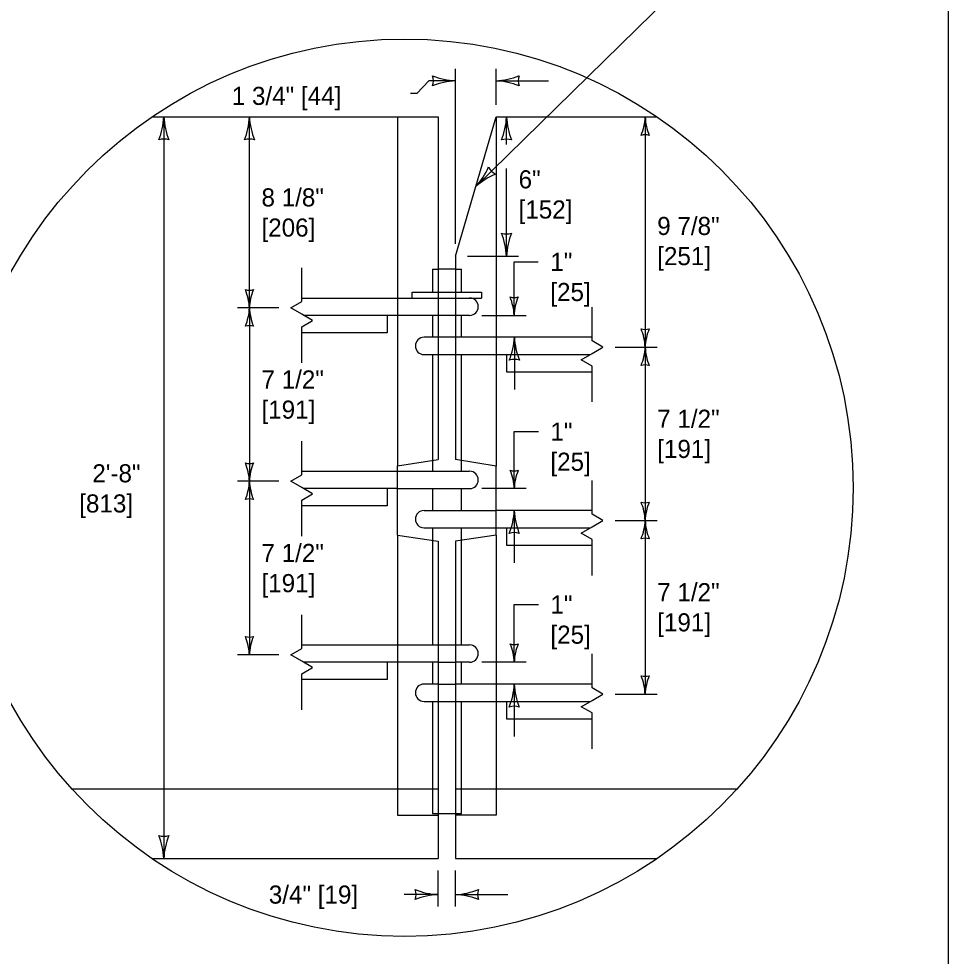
# Model space of a CAD drawing. Extents: x 49991.4 to 50021, y 49987.6 to 50011.4.
# Drawn here: x 50013.668 to 50016.75, y 49992.032 to 49995.141 of the extents above; entities that cross this region are included whole.
import ezdxf

# ---------------------------------------------------------------- set-up
doc = ezdxf.new("R2010")
doc.units = 0
for name, color, linetype in [('Level 1', 7, 'Continuous'), ('Level 2', 7, 'Continuous'), ('Level 3', 7, 'Continuous'), ('Level 4', 7, 'Continuous'), ('Level 6', 7, 'Continuous')]:
    doc.layers.add(name, color=color, linetype=linetype)

msp = doc.modelspace()

# ---------------------------------------------------------------- linework, layer by layer
at = {"layer": 'Level 1'}
for p, q in [((50014.1093, 49994.815), (50015.0589, 49994.815)), ((50015.0589, 49994.815), (50015.0589, 49993.6791)), ((50015.1164, 49994.354), (50015.2508, 49994.815)), ((50015.2508, 49994.815), (50015.7852, 49994.815)), ((50015.1164, 49994.354), (50015.1164, 49993.6791)), ((50015.1164, 49994.3108), (50015.0589, 49994.3108)), ((50015.0589, 49994.234), (50015.1164, 49994.234)), ((50015.0589, 49994.2148), (50015.1164, 49994.2148)), ((50015.1164, 49994.1573), (50015.0589, 49994.1573)), ((50015.1164, 49994.0848), (50015.0589, 49994.0848)), ((50015.0589, 49994.0272), (50015.1164, 49994.0272)), ((50014.9245, 49993.6586), (50015.0589, 49993.6791)), ((50015.0396, 49993.6762), (50015.0396, 49993.6402)), ((50015.2508, 49993.6577), (50015.1164, 49993.6791)), ((50015.1357, 49993.6402), (50015.1357, 49993.676)), ((50014.9245, 49993.4288), (50014.9245, 49993.6586)), ((50014.9245, 49993.6402), (50015.1633, 49993.6402)), ((50015.2508, 49993.4288), (50015.2508, 49993.6577)), ((50014.9245, 49993.5828), (50015.1633, 49993.5828)), ((50015.0396, 49993.5828), (50015.0396, 49993.5102)), ((50015.1357, 49993.5102), (50015.1357, 49993.5828)), ((50015.0121, 49993.5102), (50015.2508, 49993.5102)), ((50015.0121, 49993.4528), (50015.2508, 49993.4528)), ((50015.0396, 49993.4528), (50015.0396, 49993.4113)), ((50015.1357, 49993.4113), (50015.1357, 49993.4528)), ((50014.9245, 49993.4288), (50015.0589, 49993.4084)), ((50015.2508, 49993.4288), (50015.1164, 49993.4084)), ((50015.0589, 49993.4084), (50015.0589, 49992.3567)), ((50015.1164, 49993.4084), (50015.1164, 49992.3567)), ((50015.0589, 49993.0647), (50015.1164, 49993.0647)), ((50015.0589, 49993.0072), (50015.1164, 49993.0072)), ((50015.0589, 49992.9346), (50015.1164, 49992.9346)), ((50015.0589, 49992.8772), (50015.1164, 49992.8772)), ((50015.0589, 49992.5055), (50015.1164, 49992.5055)), ((50014.1091, 49992.3567), (50015.0589, 49992.3567)), ((50015.1164, 49992.3567), (50015.7852, 49992.3567))]:
    msp.add_line(p, q, dxfattribs=at)
msp.add_lwpolyline([(49999.3835, 49998.9992), (50016.7501, 49998.9992), (50016.7501, 49987.7988), (49999.3835, 49987.7988)], close=True, dxfattribs=at)
for centre, start, end in [((50015.1633, 49993.6115), 270, 90), ((50015.0121, 49993.4815), 90, 270)]:
    msp.add_arc(centre, 0.0287, start, end, dxfattribs=at)
at = {"layer": 'Level 3'}
for p, q in [((50016.0589, 49995.4418), (50015.1836, 49994.5845)), ((50015.1164, 49994.394), (50015.1164, 49994.975)), ((50015.2508, 49994.855), (50015.2508, 49994.975)), ((50015.1164, 49994.935), (50015.0279, 49994.935)), ((50015.2508, 49994.935), (50015.4243, 49994.935)), ((50014.1493, 49994.815), (50014.1493, 49992.3567)), ((50014.4331, 49994.1818), (50014.4331, 49994.815)), ((50015.2856, 49994.7243), (50015.2856, 49994.815)), ((50015.7452, 49994.815), (50015.7452, 49994.0518)), ((50015.2856, 49994.354), (50015.2856, 49994.6443)), ((50015.1564, 49994.354), (50015.3256, 49994.354)), ((50015.3107, 49994.1576), (50015.3107, 49994.3347)), ((50015.3107, 49994.3347), (50015.3907, 49994.3347)), ((50014.5301, 49994.1818), (50014.3932, 49994.1818)), ((50014.4331, 49994.1818), (50014.4331, 49993.6072)), ((50015.2033, 49994.1573), (50015.3507, 49994.1573)), ((50015.3116, 49994.0848), (50015.3116, 49993.9113)), ((50015.6453, 49994.0518), (50015.7852, 49994.0518)), ((50015.7452, 49994.0518), (50015.7452, 49993.4771)), ((50015.3111, 49993.7719), (50015.3911, 49993.7719)), ((50015.3111, 49993.5827), (50015.3111, 49993.7719)), ((50014.5301, 49993.6072), (50014.3931, 49993.6072)), ((50014.4331, 49993.6072), (50014.4331, 49993.0317)), ((50015.3511, 49993.5827), (50015.2032, 49993.5827)), ((50015.3111, 49993.5102), (50015.3111, 49993.3368)), ((50015.6453, 49993.4771), (50015.7852, 49993.4771)), ((50015.7452, 49993.4771), (50015.7452, 49992.9016)), ((50015.3111, 49993.0071), (50015.3111, 49993.1985)), ((50015.3111, 49993.1985), (50015.3911, 49993.1985)), ((50014.5301, 49993.0317), (50014.3931, 49993.0317)), ((50015.3511, 49993.0071), (50015.2032, 49993.0071)), ((50015.3111, 49992.9346), (50015.3111, 49992.7611)), ((50015.6453, 49992.9016), (50015.7852, 49992.9016)), ((50015.0589, 49992.1967), (50015.0589, 49992.3167)), ((50015.1164, 49992.1967), (50015.1164, 49992.3167)), ((50015.0589, 49992.2367), (50014.946, 49992.2367)), ((50015.1164, 49992.2367), (50015.2898, 49992.2367))]:
    msp.add_line(p, q, dxfattribs=at)
msp.add_lwpolyline([(50015.0279, 49994.935), (50014.9881, 49994.8926), (50014.9667, 49994.8926)], dxfattribs=at)
msp.add_circle((50014.9472, 49993.5858), 1.4876, dxfattribs=at)
for centre, radius, start, end in [((50015.1256, 49995.1571), 0.2223, 247.456, 267.6395), ((50014.9882, 49994.935), 0.0548, 342.1388, 17.8612), ((50015.1279, 49994.7022), 0.233, 92.8273, 112.0772), ((50015.2393, 49995.1677), 0.233, 272.8273, 292.0772), ((50015.2417, 49994.7128), 0.2223, 67.456, 87.6395), ((50015.3791, 49994.935), 0.0548, 162.1388, 197.8612), ((50013.9271, 49994.8242), 0.2223, 337.456, 357.6395), ((50014.382, 49994.8265), 0.233, 182.8273, 202.0772), ((50014.211, 49994.8242), 0.2223, 337.456, 357.6395), ((50014.6659, 49994.8265), 0.233, 182.8273, 202.0772), ((50015.0634, 49994.8241), 0.2223, 337.456, 357.6395), ((50015.5183, 49994.8264), 0.233, 182.8273, 202.0772), ((50015.5675, 49994.8223), 0.1779, 337.456, 357.6395), ((50015.9314, 49994.8242), 0.1864, 182.8273, 202.0772), ((50015.7452, 49994.7124), 0.0438, 72.1388, 107.8612), ((50014.1493, 49994.6868), 0.0548, 72.1388, 107.8612), ((50014.4331, 49994.6868), 0.0548, 72.1388, 107.8612), ((50015.2856, 49994.6867), 0.0548, 72.1388, 107.8612), ((50015.0126, 49994.7427), 0.233, 317.2321, 336.4819), ((50015.3325, 49994.4194), 0.2223, 111.8608, 132.0443), ((50015.2752, 49994.6742), 0.0548, 206.5436, 242.2659), ((50015.2856, 49994.4822), 0.0548, 252.1388, 287.8612), ((50015.0528, 49994.3425), 0.233, 2.8273, 22.0772), ((50015.5077, 49994.3449), 0.2223, 157.456, 177.6395), ((50014.4331, 49994.2843), 0.0438, 252.1388, 287.8612), ((50014.247, 49994.1726), 0.1864, 2.8273, 22.0772), ((50014.6109, 49994.1744), 0.1779, 157.456, 177.6395), ((50015.3107, 49994.2599), 0.0438, 252.1388, 287.8612), ((50015.1246, 49994.1481), 0.1864, 2.8273, 22.0772), ((50015.4884, 49994.15), 0.1779, 157.456, 177.6395), ((50014.2554, 49994.1891), 0.1779, 337.456, 357.6395), ((50014.6193, 49994.191), 0.1864, 182.8273, 202.0772), ((50014.4331, 49994.0792), 0.0438, 72.1388, 107.8612), ((50015.7452, 49994.1543), 0.0438, 252.1388, 287.8612), ((50015.559, 49994.0426), 0.1864, 2.8273, 22.0772), ((50015.9229, 49994.0444), 0.1779, 157.456, 177.6395), ((50015.0894, 49994.094), 0.2223, 337.456, 357.6395), ((50015.5443, 49994.0963), 0.233, 182.8273, 202.0772), ((50015.5675, 49994.0591), 0.1779, 337.456, 357.6395), ((50015.9314, 49994.0609), 0.1864, 182.8273, 202.0772), ((50015.3116, 49993.9566), 0.0548, 72.1388, 107.8612), ((50015.7452, 49993.9492), 0.0438, 72.1388, 107.8612), ((50014.4331, 49993.7098), 0.0438, 252.1388, 287.8612), ((50014.247, 49993.598), 0.1864, 2.8273, 22.0772), ((50014.6109, 49993.5999), 0.1779, 157.456, 177.6395), ((50015.3111, 49993.6853), 0.0438, 252.1388, 287.8612), ((50015.125, 49993.5735), 0.1864, 2.8273, 22.0772), ((50015.4888, 49993.5754), 0.1779, 157.456, 177.6395), ((50014.2554, 49993.6145), 0.1779, 337.456, 357.6395), ((50014.6193, 49993.6164), 0.1864, 182.8273, 202.0772), ((50014.4331, 49993.5046), 0.0438, 72.1388, 107.8612), ((50015.7452, 49993.5797), 0.0438, 252.1388, 287.8612), ((50015.559, 49993.4679), 0.1864, 2.8273, 22.0772), ((50015.9229, 49993.4698), 0.1779, 157.456, 177.6395), ((50015.089, 49993.5194), 0.2223, 337.456, 357.6395), ((50015.5439, 49993.5217), 0.233, 182.8273, 202.0772), ((50015.5675, 49993.4844), 0.1779, 337.456, 357.6395), ((50015.9314, 49993.4863), 0.1864, 182.8273, 202.0772), ((50015.3111, 49993.382), 0.0548, 72.1388, 107.8612), ((50015.7452, 49993.3745), 0.0438, 72.1388, 107.8612), ((50014.4331, 49993.1342), 0.0438, 252.1388, 287.8612), ((50014.247, 49993.0225), 0.1864, 2.8273, 22.0772), ((50014.6109, 49993.0244), 0.1779, 157.456, 177.6395), ((50015.3111, 49993.1096), 0.0438, 252.1388, 287.8612), ((50015.125, 49992.9979), 0.1864, 2.8273, 22.0772), ((50015.4888, 49992.9997), 0.1779, 157.456, 177.6395), ((50015.7452, 49993.0042), 0.0438, 252.1388, 287.8612), ((50015.559, 49992.8924), 0.1864, 2.8273, 22.0772), ((50015.9229, 49992.8943), 0.1779, 157.456, 177.6395), ((50015.089, 49992.9437), 0.2223, 337.456, 357.6395), ((50015.5438, 49992.946), 0.233, 182.8273, 202.0772), ((50015.3111, 49992.8063), 0.0548, 72.1388, 107.8612), ((50014.1493, 49992.4849), 0.0548, 252.1388, 287.8612), ((50013.9165, 49992.3452), 0.233, 2.8273, 22.0772), ((50014.3714, 49992.3475), 0.2223, 157.456, 177.6395), ((50015.0681, 49992.4588), 0.2223, 247.456, 267.6395), ((50014.9307, 49992.2367), 0.0548, 342.1388, 17.8612), ((50015.0704, 49992.004), 0.233, 92.8273, 112.0772), ((50015.1049, 49992.4694), 0.233, 272.8273, 292.0772), ((50015.1072, 49992.0146), 0.2223, 67.456, 87.6395), ((50015.2446, 49992.2367), 0.0548, 162.1388, 197.8612)]:
    msp.add_arc(centre, radius, start, end, dxfattribs=at)
at = {"layer": 'Level 4'}
for p, q in [((50014.9245, 49994.815), (50014.9245, 49993.6586)), ((50015.2508, 49994.8148), (50015.2508, 49993.6577)), ((50015.0396, 49994.3108), (50015.0589, 49994.3108)), ((50015.0396, 49994.3108), (50015.0396, 49994.234)), ((50015.1164, 49994.3108), (50015.1357, 49994.3108)), ((50015.1357, 49994.234), (50015.1357, 49994.3108)), ((50014.9724, 49994.2148), (50014.9724, 49994.234)), ((50014.9724, 49994.234), (50015.0589, 49994.234)), ((50015.1164, 49994.234), (50015.2028, 49994.234)), ((50015.2028, 49994.234), (50015.2028, 49994.2148)), ((50014.6064, 49994.2148), (50015.0589, 49994.2148)), ((50015.1164, 49994.2148), (50015.2028, 49994.2148)), ((50015.0589, 49994.1573), (50014.6125, 49994.1573)), ((50014.8896, 49994.1573), (50014.8896, 49994.0998)), ((50015.0396, 49994.1573), (50015.0396, 49994.0848)), ((50015.1632, 49994.1573), (50015.1164, 49994.1573)), ((50015.1357, 49994.0848), (50015.1357, 49994.1573)), ((50014.8896, 49994.0998), (50014.6064, 49994.0998)), ((50015.0589, 49994.0848), (50015.0121, 49994.0848)), ((50015.569, 49994.0848), (50015.1164, 49994.0848)), ((50015.0121, 49994.0272), (50015.0589, 49994.0272)), ((50015.0396, 49994.0272), (50015.0396, 49993.6761)), ((50015.1164, 49994.0272), (50015.5626, 49994.0272)), ((50015.1357, 49993.676), (50015.1357, 49994.0272)), ((50015.2857, 49994.0272), (50015.2857, 49993.97)), ((50015.2857, 49993.97), (50015.569, 49993.97)), ((50014.6064, 49993.6402), (50014.9245, 49993.6402)), ((50014.9245, 49993.5828), (50014.6127, 49993.5828)), ((50014.8896, 49993.5828), (50014.8896, 49993.5253)), ((50014.8896, 49993.5253), (50014.6064, 49993.5253)), ((50015.569, 49993.5102), (50015.2508, 49993.5102)), ((50015.2508, 49993.4528), (50015.563, 49993.4528)), ((50015.2857, 49993.4528), (50015.2857, 49993.3952)), ((50014.9245, 49993.4288), (50014.9245, 49992.5004)), ((50015.0396, 49993.4113), (50015.0396, 49993.0647)), ((50015.1357, 49993.0647), (50015.1357, 49993.4113)), ((50015.2508, 49993.4288), (50015.2508, 49992.5004)), ((50015.2857, 49993.3952), (50015.569, 49993.3952)), ((50014.6064, 49993.0647), (50015.0589, 49993.0647)), ((50015.1164, 49993.0647), (50015.1632, 49993.0647)), ((50015.0589, 49993.0072), (50014.6127, 49993.0072)), ((50014.8896, 49993.0072), (50014.8896, 49992.9497)), ((50015.0396, 49993.0072), (50015.0396, 49992.9346)), ((50015.1632, 49993.0072), (50015.1164, 49993.0072)), ((50015.1357, 49992.9346), (50015.1357, 49993.0072)), ((50014.8896, 49992.9497), (50014.6064, 49992.9497)), ((50015.0589, 49992.9346), (50015.0121, 49992.9346)), ((50015.569, 49992.9346), (50015.1164, 49992.9346)), ((50015.0121, 49992.8772), (50015.0589, 49992.8772)), ((50015.0396, 49992.8772), (50015.0396, 49992.5055)), ((50015.1164, 49992.8772), (50015.5629, 49992.8772)), ((50015.1357, 49992.5055), (50015.1357, 49992.8772)), ((50015.2857, 49992.8772), (50015.2857, 49992.8197)), ((50015.2857, 49992.8197), (50015.569, 49992.8197)), ((50015.0589, 49992.5864), (50013.8453, 49992.5864)), ((50016.0491, 49992.5864), (50015.1164, 49992.5864)), ((50014.9245, 49992.5004), (50015.0589, 49992.5004)), ((50015.0396, 49992.5055), (50015.0589, 49992.5055)), ((50015.1164, 49992.5055), (50015.1357, 49992.5055)), ((50015.2508, 49992.5004), (50015.1164, 49992.5004))]:
    msp.add_line(p, q, dxfattribs=at)
for centre, radius, start, end in [((50015.1632, 49994.1861), 0.0288, 270, 90), ((50015.0121, 49994.056), 0.0288, 90, 270), ((50015.1632, 49993.0359), 0.0287, 270, 90), ((50015.0121, 49992.9059), 0.0287, 90, 270)]:
    msp.add_arc(centre, radius, start, end, dxfattribs=at)
at = {"layer": 'Level 6'}
for p, q in [((50014.6064, 49994.2028), (50014.6064, 49994.3148)), ((50014.5701, 49994.1818), (50014.6064, 49994.2028)), ((50014.6064, 49994.1608), (50014.5701, 49994.1818)), ((50014.6427, 49994.14), (50014.6064, 49994.1608)), ((50015.569, 49994.0728), (50015.569, 49994.1848)), ((50014.6064, 49994.119), (50014.6427, 49994.14)), ((50014.6064, 49993.9998), (50014.6064, 49994.119)), ((50015.6053, 49994.0518), (50015.569, 49994.0728)), ((50015.569, 49994.0309), (50015.6053, 49994.0518)), ((50015.5327, 49994.0099), (50015.569, 49994.0309)), ((50015.569, 49993.9889), (50015.5327, 49994.0099)), ((50015.569, 49993.87), (50015.569, 49993.9889)), ((50014.6064, 49993.6283), (50014.6064, 49993.7402)), ((50014.5701, 49993.6072), (50014.6064, 49993.6283)), ((50014.6064, 49993.5864), (50014.5701, 49993.6072)), ((50015.569, 49993.4982), (50015.569, 49993.6102)), ((50014.6427, 49993.5655), (50014.6064, 49993.5864)), ((50014.6064, 49993.5444), (50014.6427, 49993.5655)), ((50014.6064, 49993.4253), (50014.6064, 49993.5444)), ((50015.6053, 49993.4772), (50015.569, 49993.4982)), ((50015.569, 49993.4562), (50015.6053, 49993.4772)), ((50015.5327, 49993.4353), (50015.569, 49993.4562)), ((50015.569, 49993.4144), (50015.5327, 49993.4353)), ((50015.569, 49993.2952), (50015.569, 49993.4144)), ((50014.6064, 49993.0525), (50014.6064, 49993.1647)), ((50014.5701, 49993.0317), (50014.6064, 49993.0525)), ((50014.6064, 49993.0108), (50014.5701, 49993.0317)), ((50014.6427, 49992.9898), (50014.6064, 49993.0108)), ((50015.569, 49992.9227), (50015.569, 49993.0346)), ((50014.6064, 49992.9688), (50014.6427, 49992.9898)), ((50014.6064, 49992.8497), (50014.6064, 49992.9688)), ((50015.6053, 49992.9016), (50015.569, 49992.9227)), ((50015.569, 49992.8807), (50015.6053, 49992.9016)), ((50015.5327, 49992.8597), (50015.569, 49992.8807)), ((50015.569, 49992.8388), (50015.5327, 49992.8597)), ((50015.569, 49992.7197), (50015.569, 49992.8388))]:
    msp.add_line(p, q, dxfattribs=at)

# ---------------------------------------------------------------- texts
at = {"layer": 'Level 2'}
for s, p in [('1 3/4" [44]', (50014.3747, 49994.855)), ('6" ', (50015.3256, 49994.5783)), ('8 1/8"', (50014.4731, 49994.5184)), ('[152]', (50015.3256, 49994.4783)), ('[206]', (50014.4731, 49994.4184)), ('9 7/8"', (50015.7852, 49994.4237)), ('[251]', (50015.7852, 49994.3237)), ('1"', (50015.4307, 49994.3047)), ('[25]', (50015.4307, 49994.2047)), ('7 1/2"', (50014.4731, 49993.9147)), ('[191]', (50014.4731, 49993.8147)), ('7 1/2"', (50015.7852, 49993.7844)), ('1"', (50015.4311, 49993.7419)), ('[191]', (50015.7852, 49993.6844)), ('[25]', (50015.4311, 49993.6419)), ('2\'-8"', (50013.9123, 49993.6036)), ('[813]', (50013.8688, 49993.5036)), ('7 1/2"', (50014.4731, 49993.3394)), ('[191]', (50014.4731, 49993.2394)), ('7 1/2"', (50015.7852, 49993.2094)), ('1"', (50015.4311, 49993.1685)), ('[191]', (50015.7852, 49993.1094)), ('[25]', (50015.4311, 49993.0685)), ('3/4" [19]', (50014.4974, 49992.2067))]:
    msp.add_text(s, height=0.06, dxfattribs=at).set_placement(p)

doc.saveas('drawing.dxf')
